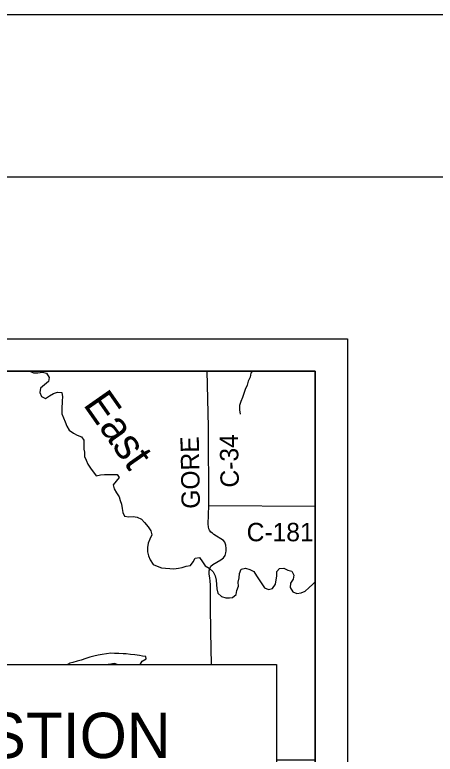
# Model space of a CAD drawing. Extents: x 0 to 34, y 0 to 22.
# Drawn here: x 7.972 to 9.271, y 19.717 to 22 of the extents above; entities that cross this region are included whole.
import ezdxf

# ---------------------------------------------------------------- set-up
doc = ezdxf.new("R2010")
doc.units = 0
for name, color, linetype in [('GM_X_Corporation', 7, 'Continuous'), ('GM_X_County_Road', 7, 'Continuous'), ('GM_X_County_Road_Text', 7, 'Continuous'), ('GM_X_Minor_Lake', 7, 'Continuous'), ('GM_X_Minor_River', 7, 'Continuous'), ('GM_X_Minor_River_Text', 7, 'Continuous'), ('GM_X_Township_Road', 7, 'Continuous'), ('SH_Border', 7, 'Continuous'), ('SH_Cut_Line', 7, 'Continuous'), ('SH_Data', 7, 'Continuous'), ('SH_Text', 7, 'Continuous')]:
    doc.layers.add(name, color=color, linetype=linetype)

msp = doc.modelspace()

# ---------------------------------------------------------------- linework, layer by layer
at = {"layer": 'GM_X_Corporation'}
msp.add_lwpolyline([(8.9, 14.1), (8.9, 20.9), (7.8853, 20.9), (7.8855, 20.8777), (7.8865, 20.8322), (7.8862, 20.7899), (7.8881, 20.7568), (7.8881, 20.7393), (7.8896, 20.6817), (7.8919, 20.5951), (7.8945, 20.502), (7.9008, 20.2877), (7.9013, 20.2705), (7.9044, 19.994), (8.7801, 19.994), (8.7801, 19.2769)], dxfattribs=at)
msp.add_lwpolyline([(8.7801, 19.7002), (8.9, 19.6997), (8.9, 20.9), (7.8853, 20.9), (7.8855, 20.8777), (7.8865, 20.8322), (7.8862, 20.7899), (7.8881, 20.7568), (7.8881, 20.7393), (7.8896, 20.6817), (7.8919, 20.5951), (7.8945, 20.502), (7.9008, 20.2877), (7.9013, 20.2705), (7.9044, 19.994), (8.7801, 19.994)], close=True, dxfattribs=at)
at = {"layer": 'GM_X_County_Road'}
msp.add_line((8.5711, 20.4855), (8.9, 20.4833), dxfattribs=at)
msp.add_lwpolyline([(8.5711, 20.4855), (8.5707, 20.7278), (8.5667, 20.9)], dxfattribs=at)
at = {"layer": 'GM_X_Minor_Lake'}
for points in [[(8.377, 20.0188), (8.3672, 20.0202), (8.3573, 20.0223), (8.3435, 20.0241), (8.3298, 20.0254), (8.3161, 20.0272), (8.3066, 20.0275), (8.2937, 20.0284), (8.2803, 20.0287), (8.2686, 20.0289), (8.2556, 20.0269), (8.2424, 20.0248), (8.2294, 20.0228), (8.2165, 20.02), (8.2044, 20.0172), (8.1915, 20.0128), (8.1775, 20.0077), (8.165, 20.0042), (8.1517, 20.0002), (8.1422, 19.9982), (8.1351, 19.994)], [(8.2746, 19.9962), (8.2746, 19.9963), (8.2617, 19.9943), (8.2605, 19.994)], [(8.2746, 19.9962), (8.2617, 19.9943), (8.2605, 19.994)], [(8.2887, 19.994), (8.2803, 19.9971), (8.2744, 19.9962)], [(8.2887, 19.994), (8.2803, 19.9971), (8.2746, 19.9962)], [(8.3592, 19.994), (8.3658, 20.005), (8.3779, 20.0116), (8.377, 20.0188)]]:
    msp.add_lwpolyline(points, dxfattribs=at)
at = {"layer": 'GM_X_Minor_River'}
for points in [[(8.0183, 20.9), (8.0301, 20.8949), (8.0438, 20.895), (8.0575, 20.8963), (8.0705, 20.8934), (8.0786, 20.8806), (8.0765, 20.8677), (8.0636, 20.8576), (8.0512, 20.8472), (8.0491, 20.8343), (8.0549, 20.8214), (8.0675, 20.8155), (8.0796, 20.8233), (8.0913, 20.831), (8.1038, 20.8349), (8.1172, 20.8339), (8.12, 20.8203), (8.119, 20.8081), (8.1177, 20.7823), (8.1179, 20.7686), (8.1222, 20.7557), (8.1277, 20.7432), (8.1328, 20.73), (8.1405, 20.7176), (8.1532, 20.7086), (8.1654, 20.7019), (8.1781, 20.6975), (8.185, 20.6869), (8.1853, 20.6595), (8.1873, 20.6497), (8.1875, 20.6368), (8.1922, 20.6247), (8.198, 20.6126), (8.2065, 20.6005), (8.2235, 20.5771), (8.2368, 20.58), (8.2494, 20.5809), (8.2623, 20.581), (8.2752, 20.5808), (8.2889, 20.5813), (8.2951, 20.5711), (8.285, 20.56), (8.2756, 20.5492), (8.2788, 20.5367), (8.2861, 20.5243), (8.2946, 20.5122), (8.2982, 20.5005), (8.3018, 20.4891), (8.3038, 20.4762), (8.3055, 20.4637), (8.3113, 20.4524), (8.3243, 20.4499), (8.3379, 20.4515), (8.3505, 20.4494), (8.3631, 20.4427), (8.3732, 20.4326), (8.384, 20.419), (8.3925, 20.4069), (8.3956, 20.3944), (8.3897, 20.3807), (8.3841, 20.3689), (8.382, 20.3559), (8.3825, 20.3422), (8.3853, 20.3301), (8.3908, 20.3169), (8.3993, 20.3033), (8.4116, 20.2977), (8.4249, 20.2926), (8.4379, 20.2912), (8.4508, 20.291), (8.4638, 20.2896), (8.4775, 20.2913), (8.4892, 20.2933), (8.5017, 20.298), (8.515, 20.2997), (8.5233, 20.3108), (8.5296, 20.3226), (8.5429, 20.3247), (8.5518, 20.3111), (8.5603, 20.2991), (8.5722, 20.2912), (8.5845, 20.2807), (8.5907, 20.2679), (8.5946, 20.255), (8.5948, 20.2413), (8.5961, 20.2276), (8.5997, 20.214), (8.6108, 20.2039), (8.6238, 20.2006), (8.6356, 20.2), (8.6451, 20.2016), (8.6556, 20.2105), (8.6585, 20.2227), (8.6629, 20.2364), (8.6624, 20.2489), (8.6649, 20.2619), (8.6663, 20.2748), (8.6711, 20.2886), (8.6848, 20.2914)], [(8.707, 20.9), (8.7011, 20.8935), (8.6994, 20.8809), (8.6931, 20.8691), (8.6902, 20.8565), (8.6838, 20.8428), (8.6798, 20.8309), (8.6754, 20.8187), (8.6706, 20.8057), (8.6665, 20.7935), (8.6659, 20.7806), (8.668, 20.767)], [(8.6848, 20.2914), (8.6981, 20.2877), (8.7108, 20.281), (8.7193, 20.2678), (8.7355, 20.2429), (8.7433, 20.2312), (8.7555, 20.2257), (8.768, 20.2285), (8.7774, 20.2419), (8.7795, 20.2552), (8.7817, 20.2674), (8.7815, 20.2811), (8.7898, 20.2907), (8.8034, 20.292), (8.8153, 20.286), (8.8279, 20.2824), (8.8341, 20.2699), (8.8324, 20.2577), (8.8241, 20.2451), (8.8231, 20.2322), (8.8309, 20.219), (8.8435, 20.2138), (8.8572, 20.2151), (8.8689, 20.2202), (8.8806, 20.2313), (8.8926, 20.2425), (8.9, 20.249)]]:
    msp.add_lwpolyline(points, dxfattribs=at)
at = {"layer": 'GM_X_Township_Road'}
msp.add_lwpolyline([(8.58, 19.994), (8.5776, 20.0947), (8.5769, 20.1745), (8.5767, 20.2402), (8.5762, 20.2513), (8.5747, 20.2619), (8.5727, 20.2734), (8.5729, 20.2834), (8.5742, 20.2911), (8.5782, 20.2975), (8.5844, 20.3033), (8.5961, 20.3101), (8.6089, 20.3174), (8.6172, 20.3238), (8.6216, 20.3311), (8.6242, 20.3389), (8.6253, 20.3453), (8.6253, 20.3521), (8.6242, 20.3623), (8.6211, 20.3718), (8.6167, 20.3771), (8.5875, 20.3953), (8.5824, 20.3997), (8.5773, 20.4032), (8.5738, 20.4086), (8.5718, 20.4132), (8.5707, 20.419), (8.57, 20.4274), (8.5711, 20.4855)], dxfattribs=at)
at = {"layer": 'SH_Border'}
msp.add_lwpolyline([(1.5, 21.5), (33.5, 21.5), (33.5, 0.5), (1.5, 0.5)], close=True, dxfattribs=at)
at = {"layer": 'SH_Cut_Line'}
msp.add_lwpolyline([(0, 0), (34, 0), (34, 22), (0, 22)], close=True, dxfattribs=at)
at = {"layer": 'SH_Data'}
for p, q in [((2, 21), (9, 21)), ((9, 21), (9, 14)), ((2.1, 20.9), (8.9, 20.9)), ((8.9, 20.9), (8.9, 14.1))]:
    msp.add_line(p, q, dxfattribs=at)
at = {"layer": 'SH_Text'}
msp.add_lwpolyline([(6.5603, 19.994), (8.7801, 19.994), (8.7801, 19.2769), (6.5603, 19.2769)], close=True, dxfattribs=at)

# ---------------------------------------------------------------- texts
at = {"layer": 'GM_X_County_Road_Text'}
for s, rotation, p in [('GORE', 91.0099, (8.5444, 20.4755)), ('C-34', 91.0299, (8.6646, 20.541)), ('C-181', 0, (8.6884, 20.3747))]:
    msp.add_text(s, height=0.05682, rotation=rotation, dxfattribs=at).set_placement(p)
at = {"layer": 'GM_X_Minor_River_Text'}
msp.add_text('East', height=0.09475, rotation=304.9949, dxfattribs=at).set_placement((8.1815, 20.7967))
at = {"layer": 'SH_Text'}
msp.add_text('END ACQUISTION', height=0.14, dxfattribs=at).set_placement((6.8413, 19.7054))

doc.saveas('drawing.dxf')
